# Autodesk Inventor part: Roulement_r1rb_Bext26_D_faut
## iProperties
Created: 2011-10
Part Number: Roulement_r1rb_Bext26_D_faut
Document SubType Name: Modeling
Designer: Bruno
Author: Bruno
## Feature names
1. Base1
